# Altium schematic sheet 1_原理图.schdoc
size 497 x 243 mm; Name: A_A4; Symbol: A_A4; Device: A_A4; @Project Name: 台州路桥中学PCB-NFC校园卡; REV: 1.0; Date: 2023-07-12; Sheet: 1/1; Draw By: era-yes; Company: Your Company; Convert to PCB: yes; Add into BOM: yes
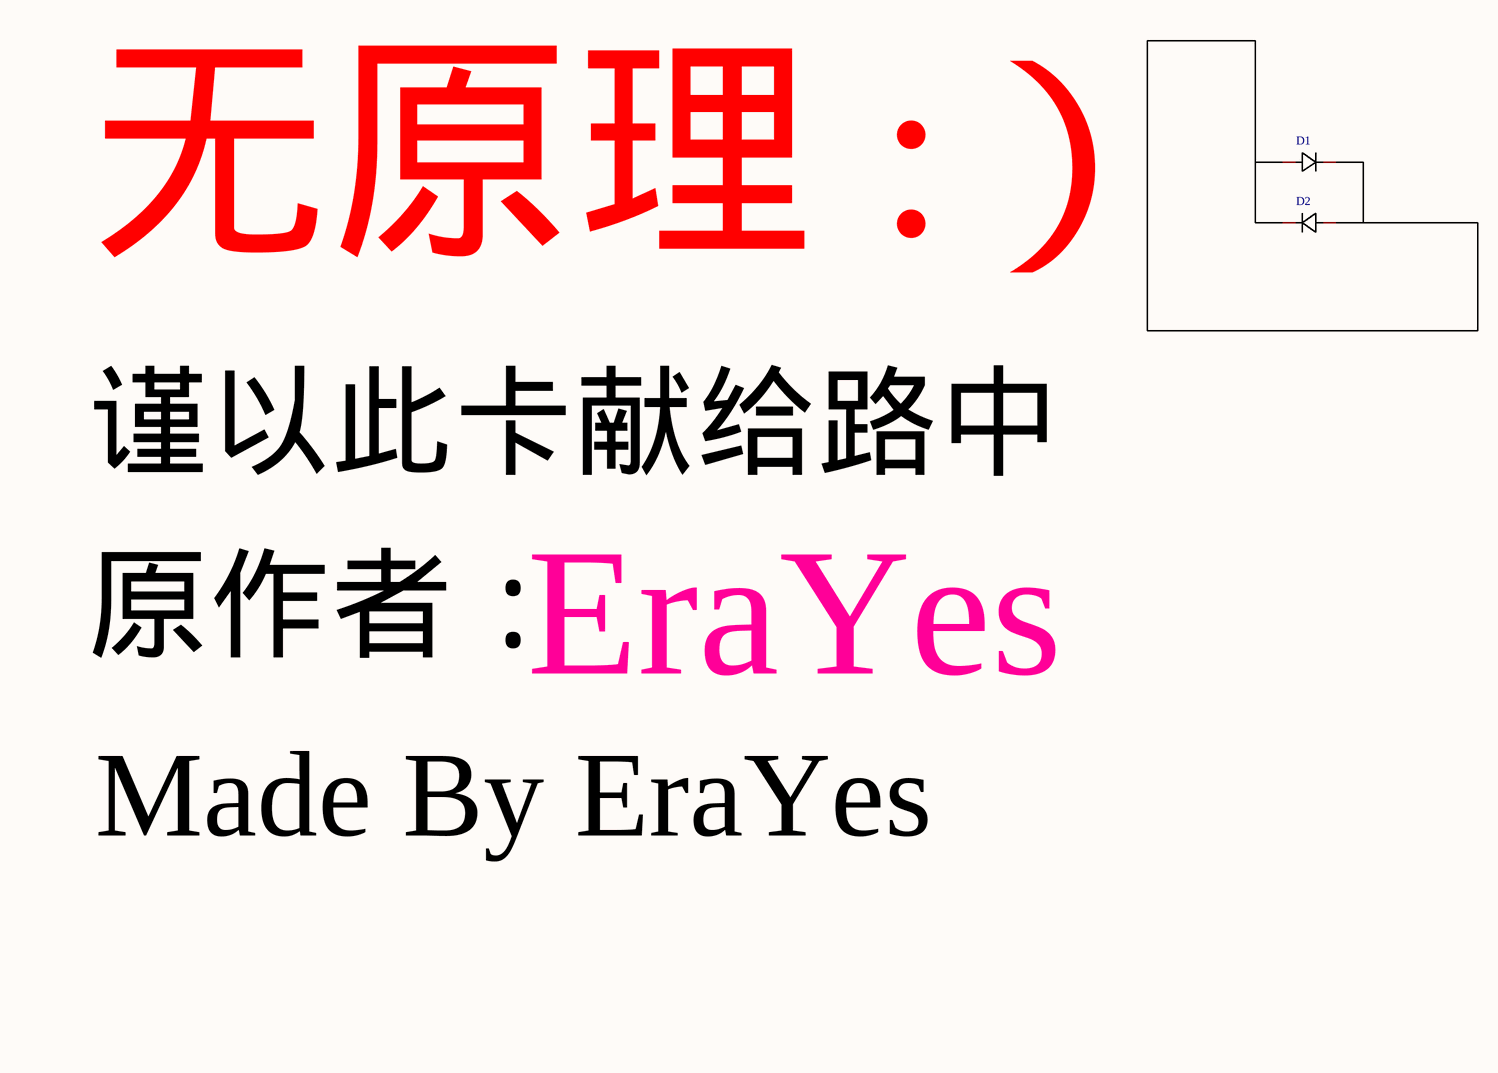
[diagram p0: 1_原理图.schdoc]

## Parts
D1  D_1N4007A  [DO_1N4007]  (value not drawn)
D2  D_1N4007A  [DO_1N4007]  (value not drawn)

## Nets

Not connected (* = marked no-connect by the designer): D1 1(K) 2(A); D2 1(K) 2(A)

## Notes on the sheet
- 无原理 :）
- 谨以此卡献给路中
- 原作者：
- EraYes
- Made By EraYes

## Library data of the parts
D1 D2 = D_1N4007A: Add into BOM: yes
